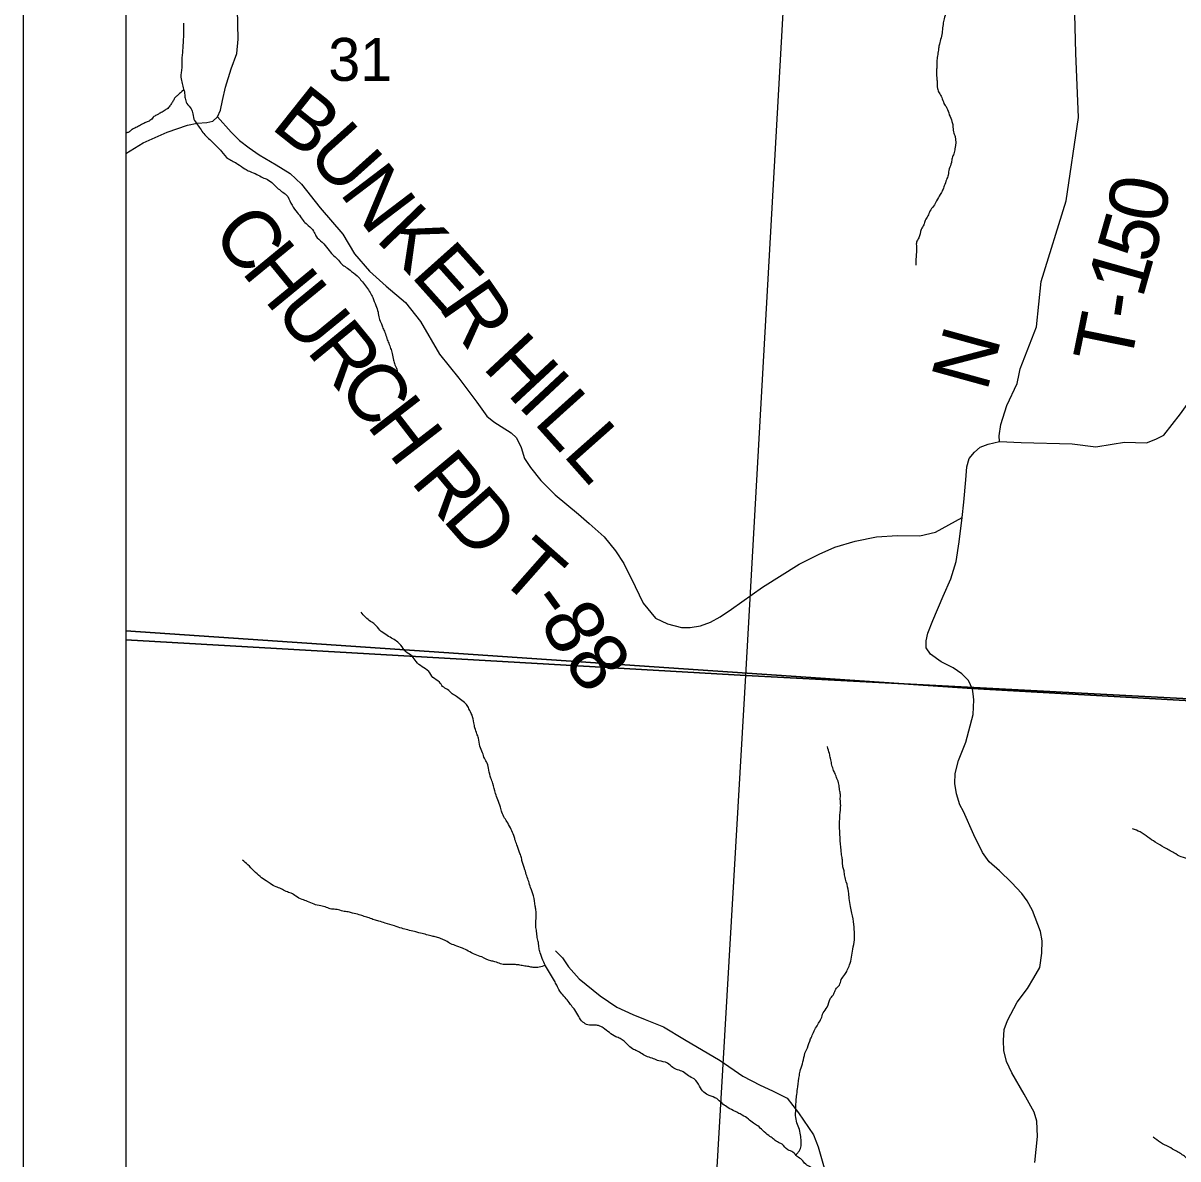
# Model space of a CAD drawing. Extents: x -20.2 to 34, y 0 to 22.
# Drawn here: x 2 to 3.126, y 18.737 to 19.844 of the extents above; entities that cross this region are included whole.
import ezdxf

# ---------------------------------------------------------------- set-up
doc = ezdxf.new("R2010")
doc.units = 0
for name, color, linetype in [('Default', 7, 'Continuous'), ('GM_X_County_Road', 7, 'Continuous'), ('GM_X_Minor_River', 7, 'Continuous'), ('GM_X_Section', 7, 'Continuous'), ('GM_X_Section_Text', 7, 'Continuous'), ('GM_X_Township_Road', 7, 'Continuous'), ('GM_X_Township_Road_Text', 7, 'Continuous'), ('SH_Cut_Line', 7, 'Continuous'), ('SH_Data', 7, 'Continuous')]:
    doc.layers.add(name, color=color, linetype=linetype)

msp = doc.modelspace()

# ---------------------------------------------------------------- linework, layer by layer
at = {"layer": 'Default'}
for points in [[(8.1508, 20.9), (2.1, 20.9), (2.1, 19.2514), (2.9253, 19.1951), (4.084, 19.1299), (4.129, 19.1285), (4.5, 19.1063), (4.5753, 19.1032), (5.0716, 19.0751), (5.6168, 19.0426), (5.628, 19.0419), (5.9006, 19.026), (6.5332, 18.9927), (7.3871, 18.9465), (7.5395, 18.9382), (7.8072, 18.9199), (8.043, 18.9097), (8.0485, 19.0914), (8.0709, 19.4522), (8.1316, 20.5548)], [(2.1, 20.265), (2.1, 19.2427), (2.7046, 19.2077), (2.7621, 20.2295)], [(2.1, 19.2427), (2.1, 18.2055), (2.6444, 18.1765), (2.7046, 19.2077)]]:
    msp.add_lwpolyline(points, close=True, dxfattribs=at)
msp.add_lwpolyline([(4.5, 19.1063), (4.129, 19.1285), (4.084, 19.1299), (2.9253, 19.1951), (2.1, 19.2514), (2.1, 14.1), (5.3953, 14.1)], dxfattribs=at)
at = {"layer": 'GM_X_County_Road'}
msp.add_lwpolyline([(2.1, 19.7168), (2.117, 19.7271), (2.1405, 19.7375), (2.1603, 19.7443), (2.1697, 19.7463), (2.179, 19.7469), (2.185, 19.7484), (2.1895, 19.7525), (2.1925, 19.7592), (2.1943, 19.7684), (2.1973, 19.7814), (2.2027, 19.7994), (2.2085, 19.8142), (2.2098, 19.8283), (2.2091, 19.8575)], dxfattribs=at)
at = {"layer": 'GM_X_Minor_River'}
for points in [[(2.9084, 20.2763), (2.9125, 20.2713), (2.9189, 20.2625), (2.9222, 20.2561), (2.9226, 20.25), (2.9225, 20.2416), (2.9217, 20.2348), (2.9216, 20.2253), (2.9216, 20.2211), (2.9219, 20.2162), (2.9223, 20.2109), (2.9226, 20.2063), (2.9237, 20.1991), (2.9248, 20.1949), (2.9274, 20.1896), (2.9285, 20.185), (2.93, 20.1801), (2.9326, 20.1747), (2.936, 20.1694), (2.9386, 20.1618), (2.9393, 20.1564), (2.9408, 20.1511), (2.9415, 20.1447), (2.9426, 20.1393), (2.9464, 20.134), (2.9505, 20.1302), (2.9539, 20.1256), (2.9573, 20.1202), (2.958, 20.113), (2.9591, 20.1062), (2.9598, 20.0982), (2.9605, 20.094), (2.9601, 20.0883), (2.9593, 20.083), (2.9585, 20.0788), (2.9569, 20.0747), (2.9558, 20.0701), (2.9534, 20.0656), (2.9515, 20.0603), (2.9481, 20.0557), (2.9442, 20.0493), (2.9423, 20.0448), (2.9404, 20.0399), (2.9373, 20.0342), (2.9353, 20.0258), (2.9337, 20.0175), (2.9329, 20.0107), (2.9321, 20.005), (2.932, 19.994), (2.9328, 19.9875), (2.9327, 19.9769), (2.9319, 19.972), (2.9307, 19.9663), (2.9288, 19.9606), (2.9257, 19.9526), (2.9229, 19.9443), (2.9195, 19.936), (2.9168, 19.928), (2.9152, 19.9227), (2.9132, 19.9151), (2.9102, 19.9076), (2.9074, 19.8981), (2.9066, 19.8939), (2.9047, 19.8833), (2.9042, 19.8791), (2.9027, 19.8723), (2.9019, 19.8682), (2.9003, 19.8594), (2.8995, 19.8549), (2.8979, 19.8481), (2.8968, 19.8427), (2.896, 19.8359), (2.8948, 19.8295), (2.8932, 19.8234), (2.8924, 19.8192), (2.8916, 19.8132), (2.8908, 19.8079), (2.8908, 19.8022), (2.8904, 19.798), (2.8907, 19.7908), (2.891, 19.7866), (2.8914, 19.7801), (2.8929, 19.776), (2.8955, 19.7714), (2.8977, 19.7657), (2.9003, 19.7615), (2.9029, 19.7546), (2.9055, 19.7481), (2.9063, 19.744), (2.907, 19.7379), (2.9085, 19.7333), (2.9084, 19.7215), (2.9072, 19.7166), (2.9057, 19.7124), (2.9049, 19.7079), (2.9029, 19.7018), (2.9017, 19.6958)], [(2.1565, 19.8439), (2.1564, 19.8344), (2.156, 19.8261), (2.1556, 19.8193), (2.1551, 19.8132), (2.1547, 19.8083), (2.1547, 19.8026), (2.1543, 19.7973), (2.1538, 19.7927), (2.1546, 19.7866), (2.156, 19.7809), (2.1575, 19.7752), (2.1579, 19.7706), (2.1597, 19.7657), (2.1639, 19.7603), (2.1653, 19.7554), (2.1672, 19.7489), (2.1709, 19.7436), (2.1743, 19.7386), (2.1781, 19.734), (2.1833, 19.7291), (2.1935, 19.7187), (2.2003, 19.7115), (2.2048, 19.7091), (2.2094, 19.7065), (2.2162, 19.7018), (2.2207, 19.6995), (2.2279, 19.6964), (2.2335, 19.6934), (2.2381, 19.6914), (2.2437, 19.6872), (2.252, 19.6799), (2.2566, 19.6765), (2.2611, 19.6685), (2.2659, 19.6608), (2.2704, 19.6551), (2.2738, 19.6505), (2.278, 19.6467), (2.2832, 19.641), (2.2855, 19.6364), (2.2915, 19.6303), (2.2972, 19.6238), (2.302, 19.618), (2.3062, 19.6142), (2.3107, 19.6088), (2.3149, 19.6058), (2.3201, 19.6019), (2.3273, 19.5958), (2.3307, 19.5916), (2.3348, 19.5866), (2.3382, 19.5813), (2.3408, 19.5763), (2.3438, 19.5687), (2.346, 19.5622), (2.3471, 19.5562), (2.3493, 19.5508), (2.3508, 19.5466), (2.3527, 19.5424), (2.3546, 19.5364), (2.3564, 19.5318), (2.3583, 19.5268), (2.3598, 19.5219), (2.3612, 19.5154), (2.3623, 19.5109), (2.3646, 19.5051), (2.3645, 19.4994)], [(2.9017, 19.6958), (2.9002, 19.6912), (2.8979, 19.6852), (2.8963, 19.681), (2.894, 19.6768), (2.8905, 19.6708), (2.8875, 19.6655), (2.884, 19.6606), (2.8821, 19.656), (2.8794, 19.6515), (2.8779, 19.6473), (2.8755, 19.6428), (2.8732, 19.6345), (2.8709, 19.6303), (2.8709, 19.6261), (2.8708, 19.6204), (2.8704, 19.614), (2.8704, 19.6079)], [(2.4855, 19.0311), (2.484, 19.0353), (2.4814, 19.0429), (2.4795, 19.0478), (2.4784, 19.052), (2.4758, 19.0577), (2.4724, 19.0642), (2.4694, 19.0688), (2.4668, 19.0745), (2.4653, 19.0795), (2.4627, 19.0867), (2.4605, 19.0928), (2.4579, 19.1027), (2.4561, 19.1076), (2.4539, 19.1156), (2.4524, 19.1225), (2.4498, 19.1271), (2.4479, 19.1324), (2.4453, 19.1389), (2.4438, 19.1468), (2.4424, 19.151), (2.4405, 19.1567), (2.4394, 19.1617), (2.4376, 19.1693), (2.4346, 19.1754), (2.4323, 19.1796), (2.4278, 19.1834), (2.4225, 19.1873), (2.4184, 19.19), (2.4138, 19.1942), (2.4089, 19.1972), (2.4059, 19.2014), (2.3995, 19.206), (2.3954, 19.2118), (2.389, 19.2164), (2.3833, 19.2214), (2.3792, 19.2267), (2.3728, 19.2313), (2.3683, 19.2374), (2.3592, 19.2443), (2.3535, 19.2478), (2.3479, 19.252), (2.343, 19.2577), (2.3388, 19.2604), (2.3339, 19.2646), (2.3294, 19.2696)], [(2.7531, 18.7404), (2.7557, 18.7431), (2.7581, 18.748), (2.7585, 18.7526), (2.7581, 18.7583), (2.7567, 18.7651), (2.7544, 18.7716), (2.753, 18.7788), (2.7534, 18.7871), (2.7535, 18.7932), (2.7543, 18.7993), (2.7551, 18.8069), (2.7567, 18.8179), (2.7579, 18.8236), (2.7602, 18.8311), (2.7622, 18.8395), (2.7645, 18.8448), (2.7676, 18.8535), (2.7699, 18.8584), (2.7726, 18.8641), (2.778, 18.8735), (2.7799, 18.8788), (2.7837, 18.8845), (2.7872, 18.8932), (2.7903, 18.8974), (2.7922, 18.9019), (2.7957, 18.906), (2.7976, 18.9113), (2.8011, 18.9163), (2.8034, 18.9204), (2.8057, 18.9257), (2.8088, 18.9409), (2.8104, 18.95), (2.8105, 18.9553), (2.8098, 18.9652), (2.808, 18.9762), (2.8065, 18.9827), (2.8054, 18.9903), (2.8047, 18.9971), (2.8025, 19.0066), (2.801, 19.0123), (2.8003, 19.0173), (2.7992, 19.0214), (2.7988, 19.0268), (2.7981, 19.0317), (2.7974, 19.0374), (2.7964, 19.0499), (2.7965, 19.0746), (2.797, 19.0811), (2.7966, 19.0872), (2.7967, 19.0917), (2.796, 19.0963), (2.7952, 19.102), (2.7934, 19.1073), (2.7915, 19.1123), (2.7897, 19.1164), (2.7882, 19.1218), (2.7871, 19.1271), (2.786, 19.1317), (2.7841, 19.1385)], [(3.8309, 18.8552), (3.8289, 18.8547), (3.8198, 18.854), (3.8118, 18.853), (3.803, 18.8507), (3.7932, 18.8501), (3.7803, 18.8585), (3.7724, 18.8654), (3.7641, 18.8723), (3.7562, 18.8777), (3.746, 18.8823), (3.7373, 18.8862), (3.7289, 18.8882), (3.7214, 18.8909), (3.7119, 18.8947), (3.7021, 18.8986), (3.6937, 18.9013), (3.6858, 18.9022), (3.6759, 18.9022), (3.668, 18.9027), (3.6607, 18.902), (3.6505, 18.9009), (3.6425, 18.8957), (3.6345, 18.8931), (3.625, 18.889), (3.6166, 18.8841), (3.6078, 18.8804), (3.5987, 18.8763), (3.5892, 18.8722), (3.5743, 18.8658), (3.566, 18.8621), (3.5568, 18.8587), (3.5488, 18.8569), (3.5397, 18.8547), (3.5318, 18.854), (3.5204, 18.8552), (3.512, 18.8576), (3.5045, 18.8607), (3.4924, 18.8687), (3.4841, 18.873), (3.4754, 18.8768), (3.4663, 18.8803), (3.4557, 18.885), (3.4482, 18.8888), (3.4398, 18.8938), (3.43, 18.8992), (3.421, 18.9057), (3.4134, 18.9119), (3.4036, 18.9184), (3.3961, 18.9242), (3.3889, 18.9284), (3.3787, 18.9338), (3.3696, 18.9388), (3.3621, 18.9438), (3.353, 18.9503), (3.3421, 18.9584), (3.3326, 18.9657), (3.3228, 18.9779), (3.3149, 18.9836), (3.307, 18.9909), (3.2998, 18.9974), (3.2919, 19.0017), (3.2848, 19.0082), (3.2768, 19.0151), (3.2685, 19.0235), (3.2622, 19.0315), (3.2539, 19.0373), (3.2436, 19.0381), (3.236, 19.0351), (3.2288, 19.0337), (3.2204, 19.0322), (3.2124, 19.0304), (3.2033, 19.0289), (3.1946, 19.0286), (3.1874, 19.0283), (3.1794, 19.0287), (3.1703, 19.0288), (3.1623, 19.0277), (3.1532, 19.0271), (3.146, 19.0271), (3.1377, 19.0287), (3.129, 19.031), (3.1218, 19.0349), (3.1124, 19.0403), (3.1037, 19.0453), (3.0965, 19.0503), (3.0889, 19.0553), (3.0814, 19.0584)], [(2.5091, 18.9251), (2.4972, 18.9232), (2.493, 18.924), (2.4877, 18.9248), (2.4832, 18.9256), (2.479, 18.926), (2.471, 18.926), (2.4653, 18.9268), (2.46, 18.9288), (2.4559, 18.9296), (2.4472, 18.9334), (2.4407, 18.9358), (2.4339, 18.9392), (2.4283, 18.9419), (2.4211, 18.9446), (2.4158, 18.947), (2.4109, 18.9497), (2.4063, 18.9516), (2.4018, 18.9531), (2.3976, 18.9539), (2.3919, 18.9555), (2.3859, 18.9571), (2.3817, 18.9582), (2.3749, 18.9598), (2.3692, 18.9614), (2.362, 18.9637), (2.3529, 18.9664), (2.3469, 18.9684), (2.3423, 18.9696), (2.3374, 18.9715), (2.3325, 18.973), (2.3276, 18.9746), (2.3211, 18.9762), (2.317, 18.9773), (2.3117, 18.9781), (2.306, 18.9797), (2.3007, 18.9801), (2.2958, 18.9817), (2.2901, 18.9833), (2.2836, 18.9848), (2.2772, 18.9875), (2.2719, 18.9895), (2.2659, 18.9926), (2.2613, 18.9956), (2.2564, 18.9972), (2.2515, 18.9999), (2.2466, 19.0018), (2.2409, 19.0049), (2.2368, 19.0076), (2.2311, 19.0118), (2.2251, 19.0172), (2.219, 19.0233), (2.2138, 19.0279)], [(2.8527, 18.5718), (2.8497, 18.5768), (2.8464, 18.5837), (2.8422, 18.5875), (2.8396, 18.594), (2.834, 18.6016), (2.8302, 18.607), (2.8272, 18.6119), (2.8212, 18.6203), (2.8159, 18.6245), (2.8133, 18.6291), (2.8092, 18.6356), (2.8043, 18.6406), (2.8005, 18.6459), (2.7964, 18.6516), (2.7912, 18.6608), (2.7901, 18.665), (2.7874, 18.6699), (2.7856, 18.6756), (2.7837, 18.6806), (2.7819, 18.6867), (2.78, 18.6924), (2.7786, 18.7), (2.7775, 18.7049), (2.7748, 18.7091), (2.7737, 18.7152), (2.7719, 18.7194), (2.77, 18.724), (2.7678, 18.7282), (2.7629, 18.7313), (2.7591, 18.7358), (2.7546, 18.7389), (2.7504, 18.7431), (2.7455, 18.7454), (2.7399, 18.7508), (2.7353, 18.7531), (2.7312, 18.7562), (2.727, 18.7593), (2.721, 18.7642), (2.7161, 18.7688), (2.7119, 18.7715), (2.707, 18.7754), (2.701, 18.7792), (2.6968, 18.7815), (2.6923, 18.7838), (2.6859, 18.7873), (2.681, 18.7911), (2.6761, 18.7953), (2.6689, 18.7984), (2.6636, 18.8015), (2.6595, 18.8076), (2.6542, 18.8145), (2.6485, 18.8176), (2.6436, 18.8214), (2.638, 18.8234), (2.6334, 18.8257), (2.6281, 18.8299), (2.6198, 18.8322), (2.6145, 18.8342), (2.6088, 18.8361), (2.5983, 18.8419), (2.5941, 18.8438), (2.5892, 18.848), (2.582, 18.8538), (2.5779, 18.8557), (2.5654, 18.8642), (2.5609, 18.8665), (2.5567, 18.8669), (2.5506, 18.8673), (2.5457, 18.87), (2.5416, 18.8754), (2.5379, 18.8818), (2.5345, 18.886), (2.5315, 18.8902), (2.5232, 18.9002), (2.5202, 18.9059), (2.518, 18.9101), (2.5142, 18.9166), (2.5101, 18.9231), (2.5067, 18.9303), (2.5041, 18.9375), (2.503, 18.9421), (2.5023, 18.9474), (2.5012, 18.9524), (2.5005, 18.9581), (2.4998, 18.9634), (2.4998, 18.9676), (2.5002, 18.9736), (2.4999, 18.979), (2.4992, 18.9831), (2.4977, 18.993), (2.4947, 19.001), (2.4929, 19.0071), (2.491, 19.0124), (2.4892, 19.0185), (2.4866, 19.0265), (2.4855, 19.0311)], [(3.9178, 18.9186), (3.9097, 18.9126), (3.9025, 18.9039), (3.8952, 18.8994), (3.8872, 18.8953), (3.88, 18.8942), (3.8705, 18.8878), (3.8628, 18.8829), (3.8537, 18.8762), (3.8438, 18.8683), (3.8365, 18.86), (3.8273, 18.8521), (3.8189, 18.843), (3.8135, 18.8355), (3.8067, 18.8283), (3.8005, 18.8162), (3.794, 18.8045), (3.7878, 18.7954), (3.7847, 18.7882), (3.7759, 18.7803), (3.7664, 18.7747), (3.758, 18.771), (3.7489, 18.7684), (3.7409, 18.7669), (3.7322, 18.7651), (3.7212, 18.7625), (3.7128, 18.7607), (3.7056, 18.7585), (3.6976, 18.7551), (3.6896, 18.7514), (3.6793, 18.745), (3.6721, 18.7413), (3.6641, 18.7364), (3.6564, 18.7311), (3.6465, 18.7236), (3.6362, 18.715), (3.6278, 18.7074), (3.6201, 18.6965), (3.6105, 18.684), (3.6048, 18.6769), (3.5987, 18.6697), (3.591, 18.6618), (3.5807, 18.652), (3.5731, 18.6475), (3.5647, 18.6426), (3.5559, 18.6389), (3.5461, 18.6356), (3.5342, 18.6296), (3.5244, 18.6278), (3.5156, 18.6267), (3.5084, 18.626), (3.4997, 18.6249), (3.4906, 18.6246), (3.4799, 18.6243), (3.4712, 18.6244), (3.4617, 18.6237), (3.453, 18.6226), (3.4458, 18.6212), (3.4374, 18.6163), (3.426, 18.6114), (3.4153, 18.6092), (3.4077, 18.6093), (3.3949, 18.6132), (3.385, 18.6167), (3.3752, 18.619), (3.3649, 18.6195), (3.3577, 18.6199), (3.349, 18.6211), (3.3392, 18.6231), (3.3301, 18.6289), (3.318, 18.6332), (3.3108, 18.6363), (3.3032, 18.6401), (3.2957, 18.6443), (3.2851, 18.6516), (3.2779, 18.6536), (3.2689, 18.6586), (3.2613, 18.6632), (3.2511, 18.6682), (3.2428, 18.6717), (3.2356, 18.6744), (3.228, 18.6771), (3.2193, 18.6818), (3.2121, 18.6837), (3.203, 18.6868), (3.194, 18.6896), (3.1796, 18.6927), (3.1724, 18.6958), (3.1648, 18.7), (3.1569, 18.7039), (3.1531, 18.7111), (3.1464, 18.7211), (3.14, 18.7302), (3.1332, 18.7383), (3.1242, 18.744), (3.117, 18.7483)], [(3.117, 18.7483), (3.1087, 18.7525), (3.1015, 18.7579)]]:
    msp.add_spline(points, degree=3, dxfattribs=at)
msp.add_open_spline([(2.1566, 19.7788), (2.154, 19.7765), (2.1514, 19.7742), (2.1488, 19.7719), (2.1475, 19.7708), (2.147, 19.7691), (2.1461, 19.7677), (2.1451, 19.7662), (2.1441, 19.7647), (2.143, 19.7632), (2.1418, 19.7615), (2.1402, 19.7601), (2.1384, 19.759), (2.1365, 19.7578), (2.1346, 19.7567), (2.1327, 19.7557), (2.1313, 19.7549), (2.1299, 19.7542), (2.1285, 19.7534), (2.1266, 19.7523), (2.1255, 19.75), (2.1235, 19.7489), (2.122, 19.748), (2.1202, 19.7475), (2.1186, 19.7467), (2.1166, 19.7456), (2.1145, 19.7444), (2.1125, 19.7433), (2.1108, 19.7424), (2.1089, 19.7416), (2.1072, 19.7407), (2.1056, 19.7399), (2.1045, 19.7385), (2.103, 19.7377), (2.102, 19.7371), (2.101, 19.7368), (2.1, 19.7365)], degree=3, dxfattribs=at)
at = {"layer": 'GM_X_Section'}
for points in [[(3.8229, 20.1691), (3.7661, 19.1519), (2.7046, 19.2077), (2.7621, 20.2295)], [(3.7661, 19.1519), (3.7052, 18.1153), (2.6444, 18.1765), (2.7046, 19.2077)]]:
    msp.add_lwpolyline(points, close=True, dxfattribs=at)
at = {"layer": 'GM_X_Township_Road'}
for points in [[(2.971, 19.502), (2.9721, 19.5068), (2.988, 19.5479), (2.9923, 19.5921), (3.0168, 19.6706), (3.0287, 19.752), (3.0262, 19.8146), (3.0241, 19.9038), (3.0367, 19.975), (3.0678, 20.0386), (3.1273, 20.1008), (3.1647, 20.1442), (3.2042, 20.2092), (3.2187, 20.2804), (3.2213, 20.3428), (3.2214, 20.3445), (3.2271, 20.3734)], [(2.1895, 19.7525), (2.2029, 19.7375), (2.2111, 19.7295), (2.2205, 19.7224), (2.2302, 19.7155), (2.2466, 19.7058), (2.2605, 19.6974), (2.2713, 19.6869), (2.2896, 19.6637), (2.3116, 19.6383), (2.3232, 19.6191), (2.3376, 19.6021), (2.3538, 19.5873), (2.3727, 19.5714), (2.3873, 19.5529), (2.4059, 19.521), (2.4247, 19.4977), (2.4423, 19.4745), (2.4519, 19.4608), (2.4588, 19.4553), (2.4661, 19.4507), (2.4759, 19.4444), (2.481, 19.4396), (2.4855, 19.4303), (2.4887, 19.4194), (2.4946, 19.4106), (2.5047, 19.398), (2.5186, 19.3841), (2.5413, 19.3652), (2.5519, 19.3561), (2.5665, 19.343), (2.5776, 19.3293), (2.5855, 19.3172), (2.5966, 19.2945), (2.6046, 19.2783), (2.6165, 19.2637), (2.6281, 19.2581), (2.6417, 19.2546), (2.6503, 19.2546), (2.6602, 19.2564), (2.67, 19.2599), (2.6794, 19.265), (2.6905, 19.2725), (2.7207, 19.294), (2.7566, 19.3164), (2.776, 19.326), (2.7914, 19.3329), (2.8111, 19.3387), (2.8318, 19.3432), (2.8525, 19.3442), (2.874, 19.344), (2.8893, 19.3477), (2.9153, 19.3619)], [(2.9153, 19.3619), (2.9171, 19.377), (2.9191, 19.3987), (2.9201, 19.4114), (2.9224, 19.4194), (2.9275, 19.4257), (2.9328, 19.4305), (2.9406, 19.4333), (2.9519, 19.4361), (2.9729, 19.4351), (3.0226, 19.4338), (3.0458, 19.4308), (3.0617, 19.4333), (3.0736, 19.4353), (3.0951, 19.4348), (3.1041, 19.4384), (3.112, 19.4421), (3.1284, 19.4631), (3.1544, 19.4994), (3.1651, 19.5138), (3.1743, 19.5262)], [(2.9519, 19.4361), (2.9514, 19.4416), (2.9532, 19.4525), (2.9588, 19.4712), (2.9689, 19.4926), (2.971, 19.502)], [(2.9261, 19.1899), (2.9255, 19.1946), (2.9215, 19.2031), (2.9152, 19.2095), (2.9065, 19.2152), (2.8948, 19.2211), (2.8845, 19.2285), (2.8804, 19.2348), (2.8803, 19.2418), (2.882, 19.2492), (2.8869, 19.2616), (2.897, 19.2851), (2.9045, 19.3021), (2.9097, 19.3191), (2.9126, 19.3381), (2.9153, 19.3619)], [(2.9863, 18.7332), (2.9887, 18.7583), (2.9881, 18.7735), (2.9857, 18.7822), (2.9808, 18.7909), (2.9758, 18.7998), (2.9638, 18.8205), (2.9586, 18.8316), (2.9559, 18.8421), (2.9557, 18.8519), (2.9563, 18.8628), (2.9596, 18.8715), (2.9691, 18.8895), (2.9792, 18.9026), (2.9854, 18.9131), (2.991, 18.9231), (2.9932, 18.9371), (2.9934, 18.9491), (2.9918, 18.9584), (2.9839, 18.9788), (2.9788, 18.988), (2.9737, 18.9952), (2.9634, 19.006), (2.9519, 19.0173), (2.9417, 19.0262), (2.9353, 19.0353), (2.9268, 19.0524), (2.9166, 19.0752), (2.9132, 19.0817), (2.9099, 19.0925), (2.9083, 19.1024), (2.9085, 19.1123), (2.9119, 19.1249), (2.919, 19.1427), (2.9261, 19.1697), (2.9268, 19.1842), (2.9261, 19.1899)], [(2.5189, 18.9393), (2.5259, 18.9325), (2.5318, 18.9238), (2.5421, 18.912), (2.5624, 18.8956), (2.5788, 18.8845), (2.5944, 18.8772), (2.6063, 18.8725), (2.6244, 18.8652), (2.6448, 18.8529), (2.6795, 18.8324), (2.7017, 18.8172), (2.7185, 18.8083), (2.7305, 18.803), (2.7358, 18.8003)], [(2.7358, 18.8003), (2.7447, 18.7958), (2.756, 18.7814), (2.7706, 18.7599), (2.7751, 18.7482), (2.7834, 18.7186), (2.7883, 18.7063), (2.805, 18.6811), (2.822, 18.6554), (2.8293, 18.64), (2.8332, 18.6248), (2.8374, 18.6042), (2.8496, 18.574), (2.8729, 18.5075), (2.8808, 18.4905), (2.8856, 18.4839), (2.8935, 18.476), (2.9029, 18.4687), (2.9132, 18.464), (2.9235, 18.4622)]]:
    msp.add_lwpolyline(points, dxfattribs=at)
at = {"layer": 'SH_Cut_Line'}
msp.add_lwpolyline([(5.7735, 14.1), (8.9, 14.1), (8.9, 20.9), (2.1, 20.9), (2.1, 14.1), (5.3953, 14.1), (5.7268, 14.1076)], close=True, dxfattribs=at)
at = {"layer": 'SH_Data'}
for p, q in [((2, 21), (2, 14)), ((2.1, 20.9), (2.1, 14.1))]:
    msp.add_line(p, q, dxfattribs=at)

# ---------------------------------------------------------------- texts
at = {"layer": 'GM_X_Section_Text'}
msp.add_text('31', height=0.04186, rotation=0, dxfattribs=at).set_placement((2.2975, 19.7876))
at = {"layer": 'GM_X_Township_Road_Text'}
for s, rotation, p in [('B', 321.5273, (2.2403, 19.742)), ('U', 311.9025, (2.275, 19.7147)), ('N', 307.2072, (2.3076, 19.6784)), ('0', 79.283, (3.1115, 19.6472)), ('K', 314.0469, (2.3426, 19.633)), ('C', 309.4273, (2.1823, 19.6373)), ('5', 74.0374, (3.1006, 19.608)), ('H', 309.4288, (2.2119, 19.6013)), ('E', 311.8318, (2.377, 19.5975)), ('1', 74.2254, (3.0911, 19.5744)), ('U', 309.4068, (2.2437, 19.5627)), ('R', 304.686, (2.4042, 19.5673)), ('-', 81.685, (3.0881, 19.5532)), ('R', 309.2998, (2.2754, 19.5241)), ('T', 78.4883, (3.079, 19.5082)), ('N', 74.5751, (2.9393, 19.4835)), ('H', 312.9339, (2.4468, 19.5082)), ('C', 308.9335, (2.3049, 19.488)), ('I', 313.051, (2.4809, 19.4715)), ('L', 312.0197, (2.4967, 19.4546)), ('H', 307.6648, (2.334, 19.452)), ('L', 311.604, (2.5251, 19.4231)), ('R', 309.7769, (2.3769, 19.3969)), ('D', 311.3046, (2.4078, 19.3598)), ('T', 318.5508, (2.461, 19.3041)), ('-', 306.0159, (2.4906, 19.2784)), ('8', 296.9979, (2.5031, 19.2616)), ('8', 308.2692, (2.5256, 19.2201))]:
    msp.add_text(s, height=0.0568, rotation=rotation, dxfattribs=at).set_placement(p)

doc.saveas('drawing.dxf')
